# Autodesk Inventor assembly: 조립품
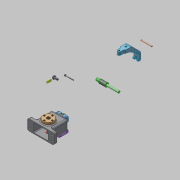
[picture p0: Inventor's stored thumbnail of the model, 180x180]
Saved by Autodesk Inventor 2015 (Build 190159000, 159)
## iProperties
Created: 2023-12
Part Number: 조립품
Document SubType Name: Assembly
Designer: 10415
Author: 10415
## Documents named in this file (14)
- C:\Users\10415\Desktop\731208V1013\조립품.iam
- C:\Users\10415\Desktop\731208V1013\본체.ipt
- C:\Users\10415\Desktop\731208V1013\가공품.ipt
- C:\Users\10415\Desktop\731208V1013\가이드 부시.ipt
- C:\Users\10415\Desktop\731208V1013\고정대.ipt
- C:\Users\10415\Desktop\731208V1013\브라켓.ipt
- C:\Users\10415\Desktop\731208V1013\스프링.ipt
- C:\Users\10415\Desktop\731208V1013\육각 머리 볼트 M6 x 12.ipt
- C:\Users\10415\Desktop\731208V1013\육각 소켓 머리 볼트 M3 x 8.ipt
- C:\Users\10415\Desktop\731208V1013\육각 소켓 머리 볼트 M3 x 30.ipt
- C:\Users\10415\Desktop\731208V1013\조절 부시.ipt
- C:\Users\10415\Desktop\731208V1013\클램프 샤프트.ipt
- C:\Users\10415\Desktop\731208V1013\클램프.ipt
- C:\Users\10415\Desktop\731208V1013\핀.ipt
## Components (4 placed, 4 different names)
1. 가공품:1
2. 가이드 부시:1
3. 고정대:1
4. 핀:1
